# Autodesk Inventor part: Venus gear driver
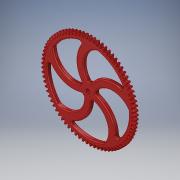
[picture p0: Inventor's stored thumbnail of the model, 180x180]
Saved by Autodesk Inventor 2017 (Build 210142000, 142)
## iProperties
Created: 2016-05
Part Number: Venus gear driver
Material: Generic
Document SubType Name: Modeling
Designer: Stan
Density: 1 g/cm^3
Appearance: Red
Author: Stan
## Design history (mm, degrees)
sketch "Sketch1"
  geometry: A1 r 26.165 centre (-20.529, -67.793) between (3.934, -77.077) and (5.192, -72.595); A2 r 26.165 centre (31.271, -63.557) between (6.672, -72.474) and (8.641, -76.692); A3 r 26.165 centre (-14.934, -69.241) between (10.204, -76.499) and (11.092, -71.931); A4 r 26.165 centre (36.347, -60.797) between (12.557, -71.689) and (14.863, -75.732); A5 r 26.165 centre (-9.241, -70.228) between (16.405, -75.413) and (16.918, -70.787); A6 r 26.165 centre (41.182, -57.632) between (18.359, -70.427) and (20.987, -74.269); A7 r 26.165 centre (-3.486, -70.747) between (22.497, -73.825) and (22.632, -69.173); A8 r 26.165 centre (45.742, -54.083) between (24.038, -68.697) and (26.971, -72.311); A9 r 26.165 centre (2.292, -70.796) between (28.44, -71.746) and (28.195, -67.098); A10 r 26.165 centre (49.998, -50.175) between (29.557, -66.509) and (32.775, -69.872); A11 r 26.165 centre (8.055, -70.374) between (34.193, -69.189) and (33.57, -64.576); A12 r 26.165 centre (53.921, -45.933) between (34.88, -63.878) and (38.361, -66.968); A13 r 26.165 centre (13.764, -69.483) between (39.719, -66.172) and (38.722, -61.625); A14 r 26.165 centre (57.486, -41.385) between (39.971, -60.823) and (43.692, -63.618); A15 r 26.165 centre (19.382, -68.13) between (44.98, -62.714) and (43.616, -58.264); A16 r 26.165 centre (60.668, -36.561) between (44.795, -57.362) and (48.732, -59.845); A17 r 26.165 centre (24.871, -66.323) between (49.943, -58.839) and (48.22, -54.515); A18 r 26.165 centre (63.446, -31.495) between (49.322, -53.52) and (53.448, -55.674); A19 r 26.165 centre (30.194, -64.075) between (54.572, -54.572) and (52.503, -50.403); A20 r 26.165 centre (65.802, -26.218) between (53.52, -49.322) and (57.808, -51.132); A21 r 26.165 centre (35.316, -61.401) between (58.839, -49.943) and (56.436, -45.956); A22 r 26.165 centre (67.72, -20.768) between (57.362, -44.795) and (61.783, -46.25); A23 r 26.165 centre (40.203, -58.318) between (62.714, -44.98) and (59.995, -41.203); A24 r 26.165 centre (69.188, -15.179) between (60.823, -39.971) and (65.348, -41.061); A25 r 26.165 centre (44.823, -54.847) between (66.172, -39.719) and (63.153, -36.176); A26 r 26.165 centre (70.195, -9.489) between (63.878, -34.88) and (68.477, -35.598); A27 r 26.165 centre (49.145, -51.011) between (69.189, -34.193) and (65.892, -30.908); A28 r 26.165 centre (70.735, -3.736) between (66.509, -29.557) and (71.151, -29.898); A29 r 26.165 centre (53.139, -46.836) between (71.746, -28.44) and (68.192, -25.434); A30 r 26.165 centre (70.804, 2.042) between (68.697, -24.038) and (73.351, -23.999); A31 r 26.165 centre (56.78, -42.349) between (73.825, -22.497) and (70.038, -19.791); A32 r 26.165 centre (70.402, 7.807) between (70.427, -18.359) and (75.063, -17.94); A33 r 26.165 centre (60.043, -37.58) between (75.413, -16.405) and (71.418, -14.017); A34 r 26.165 centre (69.531, 13.519) between (71.689, -12.557) and (76.275, -11.762); A35 r 26.165 centre (62.906, -32.56) between (76.499, -10.204) and (72.323, -8.149); A36 r 26.165 centre (68.198, 19.141) between (72.474, -6.672) and (76.98, -5.506); A37 r 26.165 centre (65.35, -27.325) between (77.077, -3.934) and (72.747, -2.227); A38 r 26.165 centre (66.411, 24.636) between (72.777, -0.742) and (77.173, 0.787); A39 r 26.165 centre (67.36, -21.907) between (77.141, 2.361) and (72.686, 3.71); A40 r 26.165 centre (64.182, 29.968) between (72.595, 5.192) and (76.852, 7.075); A41 r 26.165 centre (68.922, -16.344) between (76.692, 8.641) and (72.142, 9.622); A42 r 26.165 centre (61.525, 35.099) between (71.931, 11.092) and (76.02, 13.315); A43 r 26.165 centre (70.025, -10.672) between (75.732, 14.863) and (71.118, 15.471); A44 r 26.165 centre (58.46, 39.997) between (70.787, 16.918) and (74.681, 19.467); A45 r 26.165 centre (70.661, -4.928) between (74.269, 20.987) and (69.62, 21.216); A46 r 26.165 centre (55.005, 44.629) between (69.173, 22.632) and (72.846, 25.49); A47 r 26.165 centre (70.828, 0.847) between (72.311, 26.971) and (67.659, 26.82); A48 r 26.165 centre (51.184, 48.964) between (67.098, 28.195) and (70.526, 31.343); A49 r 26.165 centre (70.523, 6.618) between (69.872, 32.775) and (65.248, 32.246); A50 r 26.165 centre (47.023, 52.973) between (64.576, 33.57) and (67.737, 36.987); A51 r 26.165 centre (69.749, 12.344) between (66.968, 38.361) and (62.402, 37.457); A52 r 26.165 centre (42.549, 56.63) between (61.625, 38.722) and (64.496, 42.385); A53 r 26.165 centre (68.511, 17.988) between (63.618, 43.692) and (59.142, 42.418); A54 r 26.165 centre (37.791, 59.909) between (58.264, 43.616) and (60.827, 47.501); A55 r 26.165 centre (66.817, 23.513) between (59.845, 48.732) and (55.487, 47.098); A56 r 26.165 centre (32.782, 62.79) between (54.515, 48.22) and (56.753, 52.301); A57 r 26.165 centre (64.678, 28.881) between (55.674, 53.448) and (51.464, 51.464); A58 r 26.165 centre (27.555, 65.254) between (50.403, 52.503) and (52.301, 56.753); A59 r 26.165 centre (62.109, 34.056) between (51.132, 57.808) and (47.098, 55.487); A60 r 26.165 centre (22.145, 67.282) between (45.956, 56.436) and (47.501, 60.827); A61 r 26.165 centre (59.126, 39.005) between (46.25, 61.783) and (42.418, 59.142); A62 r 26.165 centre (16.587, 68.864) between (41.203, 59.995) and (42.385, 64.496); A63 r 26.165 centre (55.75, 43.695) between (41.061, 65.348) and (37.457, 62.402); A64 r 26.165 centre (10.919, 69.986) between (36.176, 63.153) and (36.987, 67.737)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; 1 further point
  constraints: 616 point on circle, 308 centre point, 4 horizontal alignment, 920 other
  dimensions: "d0" = 0 dimension on point (0, 0); "d1" = 0 dimension on point (0, 0)
extrude "Extrusion1" new body sketch "Sketch1" distance "d2" = 6.35; taper "d3" = 0 deg
sketch "Sketch2"
  geometry: A1 r 66.675 centre (0, 0) between (60.889, 27.168) and (15.057, 64.953); A2 r 32.798 centre (24.725, 33.612) between (15.057, 64.953) and (-0.532, 12.689); A3 r 45.341 centre (40.928, -13.543) between (60.889, 27.168) and (3.59, 12.182); A4 r 12.7 centre (0, 0) between (3.59, 12.182) and (-0.532, 12.689); A5 r 12.7 centre (0, 0) between (6.724, -10.774) and (7.889, -9.953); A6 r 32.798 centre (-24.327, 33.901) between (-57.121, 34.391) and (-12.232, 3.415); A7 r 12.7 centre (0, 0) between (-10.476, 7.179) and (-12.232, 3.415); A8 r 45.341 centre (25.528, 34.739) between (-7.022, 66.304) and (-10.476, 7.179); A9 r 66.675 centre (0, 0) between (-7.022, 66.304) and (-57.121, 34.391); A10 r 32.798 centre (-39.76, -12.66) between (-50.359, -43.698) and (-7.028, -10.578); A11 r 12.7 centre (0, 0) between (-10.065, -7.745) and (-7.028, -10.578); A12 r 45.341 centre (-25.151, 35.013) between (-65.229, 13.811) and (-10.065, -7.745); A13 r 66.675 centre (0, 0) between (-65.229, 13.811) and (-50.359, -43.698); A14 r 32.798 centre (-0.246, -41.726) between (25.997, -61.398) and (7.889, -9.953); A15 r 12.7 centre (0, 0) between (4.256, -11.966) and (7.889, -9.953); A16 r 45.341 centre (-41.072, -13.1) between (-33.291, -57.769) and (4.256, -11.966); A17 r 66.675 centre (0, 0) between (-33.291, -57.769) and (25.997, -61.398); A18 r 32.798 centre (39.608, -13.128) between (66.426, 5.752) and (11.903, 4.427); A19 r 12.7 centre (0, 0) between (12.695, 0.35) and (11.903, 4.427); A20 r 45.341 centre (-0.233, -43.109) between (44.654, -49.514) and (12.695, 0.35); A21 r 66.675 centre (0, 0) between (44.654, -49.514) and (66.426, 5.752); 1 further point
  constraints: 42 point on circle, 21 centre point, 56 other
  dimensions: "d4" = 0 distance of point (0, 0) A1.centre; "d5" = 0 distance of point (0, 0) A1.centre; "d23" = 360 deg dimension on point (0, 0) A2.centre (derived)
extrude "Extrusion2" cut sketch "Sketch2" distance "d6" = 6.35; taper "d7" = 0 deg
sketch "Sketch3"
  geometry: C1 r 3.175 at (0, 0); 1 further point
  constraints: 1 centre point, 1 coincident
  dimensions: "d13" = 6.35 diameter of C1
extrude "Extrusion3" cut sketch "Sketch3" distance "d14" = 6.35; taper "d15" = 0 deg
fillet "Fillet2" dims "d26" = 3.175
fillet "Fillet3" dims "d27" = 1.524
fillet "Fillet4" dims "d28" = 1.524
fillet "Fillet5" dims "d29" = 0.762
fillet "Fillet6" dims "d30" = 0.762
fillet "Fillet7" dims "d31" = 0.762
fillet "Fillet8" dims "d32" = 0.762
fillet "Fillet9" dims "d33" = 0.762
fillet "Fillet10" dims "d34" = 0.762
fillet "Fillet11" dims "d35" = 0.762
body "Solid1"
